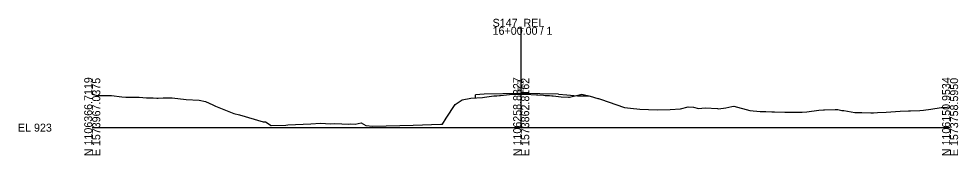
# Model space of a CAD drawing. Extents: x 1557985 to 1558314, y 1113650 to 1118205.
# Drawn here: x 1557985.4 to 1558314, y 1114150.1 to 1114198 of the extents above; entities that cross this region are included whole.
import ezdxf

# ---------------------------------------------------------------- set-up
doc = ezdxf.new("R2010")
doc.units = 0
for name, color, linetype in [('RD_GPK_XS_Cell', 7, 'Continuous'), ('RD_XS_EarthShd', 7, 'Continuous'), ('RD_XS_ExGround', 7, 'Continuous'), ('RD_XS_Pave', 7, 'Continuous'), ('RD_XS_TieSlope', 7, 'Continuous'), ('RD_XS_TX_Elev_EX', 7, 'Continuous'), ('RD_XS_TX_Elev_PR', 7, 'Continuous')]:
    doc.layers.add(name, color=color, linetype=linetype)

msp = doc.modelspace()

# ---------------------------------------------------------------- linework, layer by layer
at = {"layer": 'RD_GPK_XS_Cell'}
for p, q in [((1558161.13, 1114159.8), (1558161.13, 1114195.2)), ((1558011.13, 1114159.8), (1558161.13, 1114159.8)), ((1558161.13, 1114159.8), (1558311.13, 1114159.8))]:
    msp.add_line(p, q, dxfattribs=at)
at = {"layer": 'RD_XS_EarthShd'}
for p, q in [((1558148.13, 1114171.55), (1558145.13, 1114171.31)), ((1558174.13, 1114171.55), (1558177.13, 1114171.31)), ((1558177.13, 1114171.31), (1558180.88, 1114171.01))]:
    msp.add_line(p, q, dxfattribs=at)
at = {"layer": 'RD_XS_ExGround'}
msp.add_lwpolyline([(1558011.13, 1114171.58), (1558012.96, 1114171.08), (1558016.16, 1114171.07), (1558017.88, 1114171.11), (1558021.49, 1114170.63), (1558022.85, 1114170.51), (1558024.01, 1114170.53), (1558026.72, 1114170.53), (1558027.52, 1114170.48), (1558030.08, 1114170.31), (1558032.39, 1114170.22), (1558033.73, 1114170.2), (1558034.15, 1114170.2), (1558035.87, 1114170.26), (1558039.07, 1114170.32), (1558044.01, 1114169.72), (1558048.55, 1114169.45), (1558050.74, 1114168.99), (1558053.25, 1114167.79), (1558054.19, 1114167.31), (1558060.69, 1114164.8), (1558062.61, 1114164.27), (1558070.89, 1114161.87), (1558071.72, 1114161.84), (1558073.67, 1114160.61), (1558078.85, 1114160.67), (1558079.52, 1114160.74), (1558087.55, 1114161.11), (1558090.9, 1114161.39), (1558094.45, 1114161.16), (1558096, 1114161.26), (1558100.89, 1114161), (1558101.51, 1114161.16), (1558103.11, 1114160.97), (1558105.15, 1114161.47), (1558106.77, 1114160.52), (1558109.21, 1114160.31), (1558123.37, 1114160.66), (1558133.06, 1114161.07), (1558133.64, 1114161), (1558134.84, 1114163.17), (1558138, 1114167.9), (1558140.53, 1114169.59), (1558143.54, 1114170.12), (1558147.58, 1114170.39), (1558148.32, 1114170.48), (1558151.57, 1114170.94), (1558152.63, 1114170.98), (1558153.51, 1114171.07), (1558153.88, 1114171.1), (1558158.08, 1114171.51), (1558158.84, 1114171.52), (1558160.66, 1114171.58), (1558161.13, 1114171.59), (1558161.6, 1114171.6), (1558162.65, 1114171.53), (1558166.43, 1114171.35), (1558166.97, 1114171.31), (1558168.88, 1114171.16), (1558169.49, 1114171.13), (1558171, 1114171.04), (1558171.85, 1114170.99), (1558172.32, 1114170.94), (1558175.13, 1114170.62), (1558177.73, 1114170.49), (1558178.06, 1114170.48), (1558180.94, 1114171.22), (1558182.36, 1114171.51), (1558185.22, 1114170.86), (1558187.92, 1114169.99), (1558188.2, 1114170.05), (1558188.9, 1114169.76), (1558197.29, 1114166.87), (1558199.36, 1114166.65), (1558202.64, 1114166.26), (1558205.69, 1114166.19), (1558208.88, 1114166.06), (1558213.23, 1114166.19), (1558216.81, 1114166.37), (1558219.48, 1114167.1), (1558221.37, 1114166.95), (1558223.13, 1114166.52), (1558225.5, 1114166.72), (1558229.78, 1114166.48), (1558230.15, 1114166.39), (1558232.74, 1114166.71), (1558234.8, 1114167.18), (1558235.52, 1114167.33), (1558241.05, 1114165.88), (1558244.67, 1114165.51), (1558246.72, 1114165.43), (1558248.8, 1114165.33), (1558249.77, 1114165.31), (1558253.37, 1114165.25), (1558253.92, 1114165.25), (1558255.1, 1114165.21), (1558258.32, 1114165.18), (1558259.38, 1114165.2), (1558261.03, 1114165.41), (1558265.27, 1114165.93), (1558266.82, 1114166), (1558267.23, 1114166.02), (1558270.93, 1114166.12), (1558271.81, 1114166.12), (1558273.21, 1114165.83), (1558273.94, 1114165.79), (1558277.84, 1114165.14), (1558280.31, 1114165.09), (1558283.36, 1114165.05), (1558284, 1114165.02), (1558284.35, 1114164.99), (1558285.79, 1114165.07), (1558288.77, 1114165.2), (1558290.37, 1114165.32), (1558293.66, 1114165.61), (1558296.58, 1114165.68), (1558297.24, 1114165.72), (1558300.5, 1114165.87), (1558301.83, 1114165.93), (1558304.38, 1114166.29), (1558308.02, 1114166.86), (1558309.04, 1114166.92), (1558311.13, 1114167.09)], dxfattribs=at)
at = {"layer": 'RD_XS_Pave'}
for p, q in [((1558161.13, 1114171.81), (1558148.13, 1114171.55)), ((1558174.13, 1114171.55), (1558161.13, 1114171.81))]:
    msp.add_line(p, q, dxfattribs=at)
at = {"layer": 'RD_XS_TieSlope'}
for p, q in [((1558145.13, 1114170.22), (1558145.13, 1114171.31)), ((1558180.88, 1114171.01), (1558184.91, 1114170.93))]:
    msp.add_line(p, q, dxfattribs=at)

# ---------------------------------------------------------------- texts
at = {"layer": 'RD_GPK_XS_Cell'}
for s, p in [('S147_REL', (1558151.13, 1114195.2)), ('16+00.00 / 1', (1558151.13, 1114192.4)), ('EL 923', (1557985.13, 1114158.4))]:
    msp.add_text(s, height=2.8, dxfattribs=at).set_placement(p)
for s, p in [('N 1106366.7119', (1558011.13, 1114149.8)), ('E 1573967.0375', (1558013.93, 1114149.8)), ('N 1106258.8327', (1558161.13, 1114149.8)), ('E 1573862.8162', (1558163.93, 1114149.8)), ('N 1106150.9534', (1558311.13, 1114149.8)), ('E 1573758.5950', (1558313.93, 1114149.8))]:
    msp.add_text(s, height=2.8, rotation=90, dxfattribs=at).set_placement(p)
at = {"layer": 'RD_XS_TX_Elev_EX'}
msp.add_text('934.79', height=1, rotation=90, dxfattribs=at).set_placement((1558160.63, 1114172.09))
at = {"layer": 'RD_XS_TX_Elev_PR'}
msp.add_text(' 935.02', height=1, rotation=90, dxfattribs=at).set_placement((1558162.13, 1114171.81))

doc.saveas('drawing.dxf')
